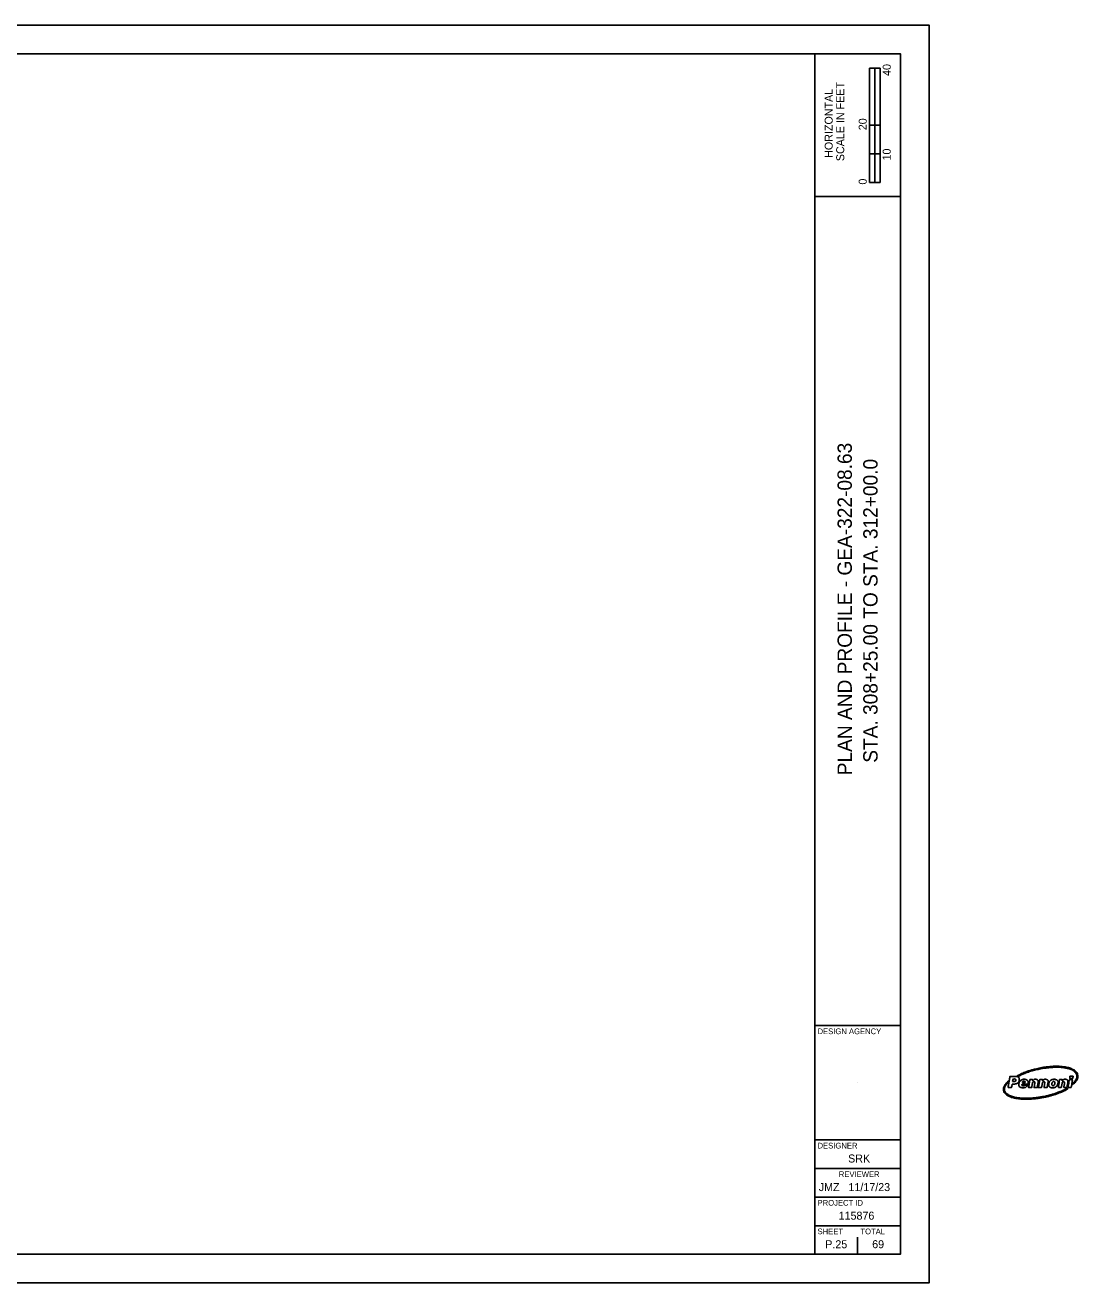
# Model space of a CAD drawing. Extents: x -0.2 to 36.6, y 0 to 22.
# Drawn here: x 18.19 to 36.6, y 0 to 22 of the extents above; entities that cross this region are included whole.
import ezdxf

# ---------------------------------------------------------------- set-up
doc = ezdxf.new("R2010")
doc.units = 0
for name, color, linetype in [('SH_Border', 7, 'Continuous'), ('SH_Cut_Line', 7, 'Continuous'), ('SH_Data', 7, 'Continuous')]:
    doc.layers.add(name, color=color, linetype=linetype)

msp = doc.modelspace()

# ---------------------------------------------------------------- linework, layer by layer
at = {"layer": 'SH_Border'}
for p, q in [((32, 0.5), (32, 21.5)), ((32, 19), (33.5, 19)), ((32, 4.5), (33.5, 4.5)), ((35.683, 3.503), (35.633, 3.503)), ((32, 2.5), (33.5, 2.5)), ((32, 2), (33.5, 2)), ((32, 1.5), (33.5, 1.5)), ((32, 1), (33.5, 1))]:
    msp.add_line(p, q, dxfattribs=at)
msp.add_lwpolyline([(1.5, 21.5), (33.5, 21.5), (33.5, 0.5), (1.5, 0.5)], close=True, dxfattribs=at)
for points, degree in [([(35.542, 3.621), (35.549, 3.619), (35.555, 3.616), (35.561, 3.615), (35.563, 3.614), (35.566, 3.614), (35.568, 3.615), (35.597, 3.629), (35.625, 3.643), (35.654, 3.655), (35.695, 3.673), (35.738, 3.688), (35.781, 3.701), (35.823, 3.714), (35.865, 3.725), (35.908, 3.734), (35.948, 3.743), (35.988, 3.751), (36.028, 3.756), (36.06, 3.76), (36.092, 3.764), (36.124, 3.767), (36.149, 3.769), (36.175, 3.77), (36.2, 3.771), (36.255, 3.772), (36.31, 3.77), (36.365, 3.762), (36.394, 3.758), (36.424, 3.752), (36.452, 3.742), (36.488, 3.731), (36.521, 3.717), (36.549, 3.691), (36.564, 3.678), (36.576, 3.661), (36.581, 3.641), (36.586, 3.624), (36.588, 3.607), (36.585, 3.589), (36.581, 3.569), (36.571, 3.552), (36.559, 3.536), (36.547, 3.521), (36.533, 3.508), (36.518, 3.495), (36.516, 3.494), (36.515, 3.492), (36.514, 3.49), (36.513, 3.485), (36.512, 3.479), (36.511, 3.473), (36.511, 3.471), (36.51, 3.469), (36.51, 3.465), (36.534, 3.485), (36.557, 3.505), (36.575, 3.529), (36.584, 3.54), (36.592, 3.553), (36.597, 3.566), (36.604, 3.585), (36.604, 3.604), (36.602, 3.623), (36.598, 3.658), (36.582, 3.685), (36.556, 3.708), (36.532, 3.728), (36.505, 3.741), (36.475, 3.752), (36.438, 3.766), (36.4, 3.774), (36.361, 3.779), (36.326, 3.784), (36.291, 3.787), (36.255, 3.788), (36.199, 3.789), (36.143, 3.787), (36.087, 3.781), (36.056, 3.777), (36.025, 3.773), (35.994, 3.768), (35.949, 3.761), (35.904, 3.752), (35.86, 3.74), (35.799, 3.725), (35.74, 3.707), (35.681, 3.684), (35.641, 3.669), (35.601, 3.651), (35.562, 3.631), (35.555, 3.628), (35.549, 3.625), (35.542, 3.621)], 3), ([(35.542, 3.621), (35.549, 3.625), (35.555, 3.628), (35.562, 3.631), (35.601, 3.651), (35.641, 3.669), (35.681, 3.684), (35.74, 3.707), (35.799, 3.725), (35.86, 3.74), (35.904, 3.752), (35.949, 3.761), (35.994, 3.768), (36.025, 3.773), (36.056, 3.777), (36.087, 3.781), (36.143, 3.787), (36.199, 3.789), (36.255, 3.788), (36.291, 3.787), (36.326, 3.784), (36.361, 3.779), (36.4, 3.774), (36.438, 3.766), (36.475, 3.752), (36.505, 3.741), (36.532, 3.728), (36.556, 3.708), (36.582, 3.685), (36.598, 3.658), (36.602, 3.623), (36.604, 3.604), (36.604, 3.585), (36.597, 3.566), (36.592, 3.553), (36.584, 3.54), (36.575, 3.529), (36.557, 3.505), (36.534, 3.485), (36.51, 3.465), (36.51, 3.469), (36.511, 3.471), (36.511, 3.473), (36.512, 3.479), (36.513, 3.485), (36.514, 3.49), (36.515, 3.492), (36.516, 3.494), (36.518, 3.495), (36.533, 3.508), (36.547, 3.521), (36.559, 3.536), (36.571, 3.552), (36.581, 3.569), (36.585, 3.589), (36.588, 3.607), (36.586, 3.624), (36.581, 3.641), (36.576, 3.661), (36.564, 3.678), (36.549, 3.691), (36.521, 3.717), (36.488, 3.731), (36.452, 3.742), (36.424, 3.752), (36.394, 3.758), (36.365, 3.762), (36.31, 3.77), (36.255, 3.772), (36.2, 3.771), (36.175, 3.77), (36.149, 3.769), (36.124, 3.767), (36.092, 3.764), (36.06, 3.76), (36.028, 3.756), (35.988, 3.751), (35.948, 3.743), (35.908, 3.734), (35.865, 3.725), (35.823, 3.714), (35.781, 3.701), (35.738, 3.688), (35.695, 3.673), (35.654, 3.655), (35.625, 3.643), (35.597, 3.629), (35.568, 3.615), (35.566, 3.614), (35.563, 3.614), (35.561, 3.615), (35.555, 3.616), (35.549, 3.619), (35.542, 3.621)], 3), ([(36.43, 3.392), (36.43, 3.392), (36.43, 3.393), (36.43, 3.393), (36.42, 3.393), (36.41, 3.393), (36.4, 3.393), (36.398, 3.393), (36.395, 3.392), (36.393, 3.391), (36.356, 3.372), (36.317, 3.355), (36.278, 3.34), (36.22, 3.317), (36.161, 3.298), (36.101, 3.283), (36.058, 3.271), (36.015, 3.262), (35.971, 3.254), (35.946, 3.25), (35.921, 3.246), (35.896, 3.242), (35.871, 3.239), (35.845, 3.236), (35.82, 3.234), (35.795, 3.232), (35.771, 3.23), (35.747, 3.23), (35.719, 3.229), (35.691, 3.228), (35.663, 3.229), (35.632, 3.231), (35.601, 3.233), (35.57, 3.236), (35.532, 3.24), (35.494, 3.248), (35.458, 3.259), (35.426, 3.269), (35.396, 3.282), (35.369, 3.302), (35.353, 3.314), (35.338, 3.329), (35.329, 3.348), (35.317, 3.374), (35.318, 3.4), (35.329, 3.427), (35.338, 3.45), (35.352, 3.47), (35.369, 3.488), (35.374, 3.494), (35.38, 3.5), (35.38, 3.509), (35.381, 3.514), (35.382, 3.52), (35.383, 3.526), (35.382, 3.525), (35.381, 3.525), (35.38, 3.524), (35.371, 3.514), (35.361, 3.505), (35.352, 3.494), (35.332, 3.472), (35.317, 3.448), (35.308, 3.419), (35.304, 3.402), (35.302, 3.385), (35.305, 3.368), (35.31, 3.341), (35.325, 3.319), (35.344, 3.301), (35.367, 3.28), (35.394, 3.266), (35.422, 3.254), (35.469, 3.235), (35.519, 3.225), (35.569, 3.219), (35.599, 3.216), (35.631, 3.214), (35.662, 3.212), (35.704, 3.211), (35.746, 3.211), (35.788, 3.215), (35.823, 3.217), (35.857, 3.221), (35.891, 3.225), (35.922, 3.229), (35.952, 3.234), (35.983, 3.239), (36.037, 3.249), (36.091, 3.261), (36.144, 3.276), (36.189, 3.289), (36.234, 3.304), (36.278, 3.321), (36.321, 3.338), (36.363, 3.356), (36.404, 3.377), (36.413, 3.382), (36.421, 3.387), (36.43, 3.392)], 3), ([(36.43, 3.392), (36.421, 3.387), (36.413, 3.382), (36.404, 3.377), (36.363, 3.356), (36.321, 3.338), (36.278, 3.321), (36.234, 3.304), (36.189, 3.289), (36.144, 3.276), (36.091, 3.261), (36.037, 3.249), (35.983, 3.239), (35.952, 3.234), (35.922, 3.229), (35.891, 3.225), (35.857, 3.221), (35.823, 3.217), (35.788, 3.215), (35.746, 3.211), (35.704, 3.211), (35.662, 3.212), (35.631, 3.214), (35.599, 3.216), (35.569, 3.219), (35.519, 3.225), (35.469, 3.235), (35.422, 3.254), (35.394, 3.266), (35.367, 3.28), (35.344, 3.301), (35.325, 3.319), (35.31, 3.341), (35.305, 3.368), (35.302, 3.385), (35.304, 3.402), (35.308, 3.419), (35.317, 3.448), (35.332, 3.472), (35.352, 3.494), (35.361, 3.505), (35.371, 3.514), (35.38, 3.524), (35.381, 3.525), (35.382, 3.525), (35.383, 3.526), (35.382, 3.52), (35.381, 3.514), (35.38, 3.509), (35.38, 3.5), (35.374, 3.494), (35.369, 3.488), (35.352, 3.47), (35.338, 3.45), (35.329, 3.427), (35.318, 3.4), (35.317, 3.374), (35.329, 3.348), (35.338, 3.329), (35.353, 3.314), (35.369, 3.302), (35.396, 3.282), (35.426, 3.269), (35.458, 3.259), (35.494, 3.248), (35.532, 3.24), (35.57, 3.236), (35.601, 3.233), (35.632, 3.231), (35.663, 3.229), (35.691, 3.228), (35.719, 3.229), (35.747, 3.23), (35.771, 3.23), (35.795, 3.232), (35.82, 3.234), (35.845, 3.236), (35.871, 3.239), (35.896, 3.242), (35.921, 3.246), (35.946, 3.25), (35.971, 3.254), (36.015, 3.262), (36.058, 3.271), (36.101, 3.283), (36.161, 3.298), (36.22, 3.317), (36.278, 3.34), (36.317, 3.355), (36.356, 3.372), (36.393, 3.391), (36.395, 3.392), (36.398, 3.393), (36.4, 3.393), (36.41, 3.393), (36.42, 3.393), (36.43, 3.393), (36.43, 3.393), (36.43, 3.392), (36.43, 3.392)], 3), ([(35.554, 3.602), (35.541, 3.608), (35.528, 3.61), (35.514, 3.61), (35.482, 3.611), (35.45, 3.61), (35.419, 3.61), (35.417, 3.61), (35.416, 3.61), (35.415, 3.608), (35.411, 3.586), (35.408, 3.565), (35.404, 3.543), (35.398, 3.509), (35.392, 3.474), (35.386, 3.439), (35.384, 3.432), (35.383, 3.424), (35.382, 3.417)], 3), ([(35.455, 3.477), (35.463, 3.477), (35.47, 3.477), (35.477, 3.477), (35.49, 3.477), (35.503, 3.477), (35.515, 3.48), (35.532, 3.483), (35.547, 3.49), (35.559, 3.502), (35.574, 3.518), (35.58, 3.537), (35.58, 3.559), (35.581, 3.578), (35.572, 3.593), (35.554, 3.602)], 3), ([(35.463, 3.522), (35.466, 3.536), (35.468, 3.55), (35.47, 3.563), (35.471, 3.564), (35.472, 3.565), (35.473, 3.565), (35.484, 3.565), (35.496, 3.567), (35.507, 3.563), (35.517, 3.56), (35.521, 3.554), (35.519, 3.543)], 3), ([(35.519, 3.543), (35.517, 3.531), (35.508, 3.523), (35.495, 3.522), (35.485, 3.522), (35.474, 3.522), (35.463, 3.522)], 3), ([(35.735, 3.508), (35.731, 3.533), (35.718, 3.55), (35.694, 3.557), (35.681, 3.562), (35.667, 3.562), (35.654, 3.561), (35.632, 3.558), (35.613, 3.549), (35.597, 3.532), (35.583, 3.517), (35.575, 3.5), (35.573, 3.479), (35.57, 3.45), (35.582, 3.426), (35.611, 3.417), (35.627, 3.412), (35.644, 3.411), (35.66, 3.414), (35.678, 3.416), (35.694, 3.422), (35.708, 3.434), (35.716, 3.441), (35.722, 3.449), (35.726, 3.459)], 3), ([(35.633, 3.503), (35.634, 3.515), (35.644, 3.525), (35.656, 3.527), (35.662, 3.528), (35.668, 3.528), (35.673, 3.525), (35.681, 3.521), (35.685, 3.513), (35.683, 3.503)], 3), ([(35.741, 3.416), (35.741, 3.415), (35.742, 3.415), (35.743, 3.415), (35.76, 3.415), (35.777, 3.415), (35.794, 3.415), (35.796, 3.415), (35.796, 3.416), (35.797, 3.418), (35.798, 3.426), (35.799, 3.435), (35.801, 3.443), (35.804, 3.46), (35.807, 3.478), (35.811, 3.495), (35.813, 3.505), (35.817, 3.513), (35.827, 3.515), (35.84, 3.519), (35.854, 3.516), (35.852, 3.497), (35.85, 3.482), (35.847, 3.468), (35.845, 3.454), (35.843, 3.441), (35.84, 3.428), (35.838, 3.416), (35.839, 3.415), (35.839, 3.415), (35.84, 3.415), (35.857, 3.415), (35.874, 3.415), (35.891, 3.415), (35.894, 3.415), (35.894, 3.416), (35.894, 3.419), (35.898, 3.442), (35.903, 3.466), (35.907, 3.49), (35.909, 3.502), (35.911, 3.515), (35.91, 3.527), (35.907, 3.543), (35.898, 3.554), (35.882, 3.558), (35.861, 3.564), (35.841, 3.56), (35.824, 3.545), (35.82, 3.542), (35.816, 3.538), (35.812, 3.535), (35.814, 3.542), (35.815, 3.549), (35.816, 3.557), (35.8, 3.557), (35.783, 3.557), (35.767, 3.556), (35.766, 3.556), (35.765, 3.555), (35.765, 3.554), (35.764, 3.55), (35.763, 3.545), (35.763, 3.541), (35.757, 3.511), (35.752, 3.48), (35.747, 3.45), (35.745, 3.438), (35.743, 3.427), (35.741, 3.416)], 3), ([(35.741, 3.416), (35.743, 3.427), (35.745, 3.438), (35.747, 3.45), (35.752, 3.48), (35.757, 3.511), (35.763, 3.541), (35.763, 3.545), (35.764, 3.55), (35.765, 3.554), (35.765, 3.555), (35.766, 3.556), (35.767, 3.556), (35.783, 3.557), (35.8, 3.557), (35.816, 3.557), (35.815, 3.549), (35.814, 3.542), (35.812, 3.535), (35.816, 3.538), (35.82, 3.542), (35.824, 3.545), (35.841, 3.56), (35.861, 3.564), (35.882, 3.558), (35.898, 3.554), (35.907, 3.543), (35.91, 3.527), (35.911, 3.515), (35.909, 3.502), (35.907, 3.49), (35.903, 3.466), (35.898, 3.442), (35.894, 3.419), (35.894, 3.416), (35.894, 3.415), (35.891, 3.415), (35.874, 3.415), (35.857, 3.415), (35.84, 3.415), (35.839, 3.415), (35.839, 3.415), (35.838, 3.416), (35.84, 3.428), (35.843, 3.441), (35.845, 3.454), (35.847, 3.468), (35.85, 3.482), (35.852, 3.497), (35.854, 3.516), (35.84, 3.519), (35.827, 3.515), (35.817, 3.513), (35.813, 3.505), (35.811, 3.495), (35.807, 3.478), (35.804, 3.46), (35.801, 3.443), (35.799, 3.435), (35.798, 3.426), (35.797, 3.418), (35.796, 3.416), (35.796, 3.415), (35.794, 3.415), (35.777, 3.415), (35.76, 3.415), (35.743, 3.415), (35.742, 3.415), (35.741, 3.415), (35.741, 3.416)], 3), ([(35.914, 3.416), (35.914, 3.415), (35.914, 3.415), (35.915, 3.415), (35.932, 3.415), (35.949, 3.415), (35.967, 3.415), (35.968, 3.415), (35.969, 3.417), (35.97, 3.418), (35.973, 3.435), (35.976, 3.452), (35.979, 3.469), (35.981, 3.479), (35.982, 3.49), (35.985, 3.5), (35.989, 3.513), (36.001, 3.519), (36.014, 3.516), (36.02, 3.515), (36.023, 3.511), (36.024, 3.505), (36.025, 3.502), (36.025, 3.499), (36.025, 3.496), (36.023, 3.485), (36.021, 3.473), (36.019, 3.462), (36.017, 3.447), (36.014, 3.431), (36.011, 3.416), (36.012, 3.415), (36.012, 3.415), (36.012, 3.415), (36.029, 3.415), (36.047, 3.415), (36.064, 3.415), (36.065, 3.415), (36.067, 3.417), (36.067, 3.418), (36.071, 3.441), (36.075, 3.463), (36.079, 3.485), (36.081, 3.497), (36.083, 3.509), (36.083, 3.522), (36.083, 3.537), (36.077, 3.55), (36.061, 3.556), (36.041, 3.564), (36.021, 3.562), (36.003, 3.55), (35.997, 3.545), (35.991, 3.54), (35.985, 3.535), (35.987, 3.543), (35.988, 3.549), (35.989, 3.557), (35.973, 3.557), (35.957, 3.557), (35.941, 3.557), (35.938, 3.557), (35.938, 3.555), (35.938, 3.553), (35.934, 3.529), (35.929, 3.505), (35.925, 3.481), (35.921, 3.46), (35.918, 3.438), (35.914, 3.416)], 3), ([(35.914, 3.416), (35.918, 3.438), (35.921, 3.46), (35.925, 3.481), (35.929, 3.505), (35.934, 3.529), (35.938, 3.553), (35.938, 3.555), (35.938, 3.557), (35.941, 3.557), (35.957, 3.557), (35.973, 3.557), (35.989, 3.557), (35.988, 3.549), (35.987, 3.543), (35.985, 3.535), (35.991, 3.54), (35.997, 3.545), (36.003, 3.55), (36.021, 3.562), (36.041, 3.564), (36.061, 3.556), (36.077, 3.55), (36.083, 3.537), (36.083, 3.522), (36.083, 3.509), (36.081, 3.497), (36.079, 3.485), (36.075, 3.463), (36.071, 3.441), (36.067, 3.418), (36.067, 3.417), (36.065, 3.415), (36.064, 3.415), (36.047, 3.415), (36.029, 3.415), (36.012, 3.415), (36.012, 3.415), (36.012, 3.415), (36.011, 3.416), (36.014, 3.431), (36.017, 3.447), (36.019, 3.462), (36.021, 3.473), (36.023, 3.485), (36.025, 3.496), (36.025, 3.499), (36.025, 3.502), (36.024, 3.505), (36.023, 3.511), (36.02, 3.515), (36.014, 3.516), (36.001, 3.519), (35.989, 3.513), (35.985, 3.5), (35.982, 3.49), (35.981, 3.479), (35.979, 3.469), (35.976, 3.452), (35.973, 3.435), (35.97, 3.418), (35.969, 3.417), (35.968, 3.415), (35.967, 3.415), (35.949, 3.415), (35.932, 3.415), (35.915, 3.415), (35.914, 3.415), (35.914, 3.415), (35.914, 3.416)], 3), ([(36.257, 3.508), (36.255, 3.53), (36.244, 3.545), (36.224, 3.554), (36.205, 3.562), (36.185, 3.562), (36.165, 3.558), (36.141, 3.553), (36.122, 3.541), (36.108, 3.52), (36.107, 3.518), (36.106, 3.515), (36.105, 3.513), (36.104, 3.511), (36.103, 3.509), (36.102, 3.507), (36.097, 3.496), (36.094, 3.484), (36.094, 3.472), (36.094, 3.47), (36.094, 3.467), (36.094, 3.465), (36.094, 3.457), (36.096, 3.45), (36.099, 3.444), (36.099, 3.443), (36.1, 3.441), (36.1, 3.44), (36.101, 3.439), (36.102, 3.438), (36.102, 3.437), (36.105, 3.434), (36.107, 3.43), (36.111, 3.427), (36.113, 3.426), (36.115, 3.424), (36.117, 3.423), (36.117, 3.422), (36.118, 3.422), (36.119, 3.422), (36.12, 3.421), (36.121, 3.42), (36.122, 3.42), (36.124, 3.419), (36.126, 3.418), (36.128, 3.417), (36.139, 3.412), (36.151, 3.411), (36.163, 3.41)], 3), ([(36.15, 3.471), (36.151, 3.487), (36.153, 3.501), (36.162, 3.513), (36.167, 3.519), (36.174, 3.523), (36.182, 3.523), (36.191, 3.523), (36.197, 3.52), (36.199, 3.511), (36.2, 3.505), (36.201, 3.498), (36.201, 3.491)], 3), ([(36.284, 3.556), (36.276, 3.509), (36.268, 3.462), (36.26, 3.415), (36.279, 3.415), (36.297, 3.415), (36.315, 3.415), (36.318, 3.43), (36.32, 3.444), (36.323, 3.458), (36.325, 3.471), (36.327, 3.484), (36.33, 3.496), (36.333, 3.51), (36.343, 3.517), (36.356, 3.517), (36.365, 3.516), (36.37, 3.511), (36.371, 3.503), (36.371, 3.5), (36.371, 3.497), (36.371, 3.494), (36.368, 3.475), (36.364, 3.456), (36.361, 3.437), (36.36, 3.43), (36.359, 3.423), (36.357, 3.415), (36.376, 3.415), (36.394, 3.415), (36.413, 3.415), (36.413, 3.417), (36.413, 3.418), (36.413, 3.419), (36.417, 3.44), (36.421, 3.462), (36.425, 3.483), (36.427, 3.497), (36.43, 3.51), (36.429, 3.525), (36.428, 3.541), (36.419, 3.553), (36.403, 3.558), (36.378, 3.565), (36.357, 3.559), (36.338, 3.541), (36.336, 3.539), (36.334, 3.537), (36.332, 3.535), (36.332, 3.535), (36.332, 3.535), (36.332, 3.536), (36.333, 3.542), (36.334, 3.549), (36.335, 3.556), (36.318, 3.556), (36.301, 3.556), (36.284, 3.556)], 3), ([(36.284, 3.556), (36.301, 3.556), (36.318, 3.556), (36.335, 3.556), (36.334, 3.549), (36.333, 3.542), (36.332, 3.536), (36.332, 3.535), (36.332, 3.535), (36.332, 3.535), (36.334, 3.537), (36.336, 3.539), (36.338, 3.541), (36.357, 3.559), (36.378, 3.565), (36.403, 3.558), (36.419, 3.553), (36.428, 3.541), (36.429, 3.525), (36.43, 3.51), (36.427, 3.497), (36.425, 3.483), (36.421, 3.462), (36.417, 3.44), (36.413, 3.419), (36.413, 3.418), (36.413, 3.417), (36.413, 3.415), (36.394, 3.415), (36.376, 3.415), (36.357, 3.415), (36.359, 3.423), (36.36, 3.43), (36.361, 3.437), (36.364, 3.456), (36.368, 3.475), (36.371, 3.494), (36.371, 3.497), (36.371, 3.5), (36.371, 3.503), (36.37, 3.511), (36.365, 3.516), (36.356, 3.517), (36.343, 3.517), (36.333, 3.51), (36.33, 3.496), (36.327, 3.484), (36.325, 3.471), (36.323, 3.458), (36.32, 3.444), (36.318, 3.43), (36.315, 3.415), (36.297, 3.415), (36.279, 3.415), (36.26, 3.415), (36.268, 3.462), (36.276, 3.509), (36.284, 3.556)], 3), ([(36.487, 3.417), (36.469, 3.417), (36.451, 3.417), (36.432, 3.417), (36.44, 3.464), (36.448, 3.51), (36.456, 3.557), (36.475, 3.557), (36.493, 3.557), (36.512, 3.557), (36.504, 3.51), (36.495, 3.464), (36.487, 3.417)], 3), ([(36.487, 3.417), (36.495, 3.464), (36.504, 3.51), (36.512, 3.557), (36.493, 3.557), (36.475, 3.557), (36.456, 3.557), (36.448, 3.51), (36.44, 3.464), (36.432, 3.417), (36.451, 3.417), (36.469, 3.417), (36.487, 3.417)], 3), ([(36.522, 3.615), (36.52, 3.603), (36.518, 3.591), (36.515, 3.578), (36.515, 3.577), (36.514, 3.576), (36.513, 3.576), (36.495, 3.576), (36.478, 3.576), (36.46, 3.576), (36.461, 3.586), (36.463, 3.595), (36.465, 3.604), (36.465, 3.606), (36.466, 3.609), (36.466, 3.611), (36.466, 3.615), (36.467, 3.615), (36.471, 3.615), (36.487, 3.615), (36.502, 3.615), (36.518, 3.615), (36.519, 3.615), (36.52, 3.615), (36.522, 3.615)], 3), ([(36.522, 3.615), (36.52, 3.615), (36.519, 3.615), (36.518, 3.615), (36.502, 3.615), (36.487, 3.615), (36.471, 3.615), (36.467, 3.615), (36.466, 3.615), (36.466, 3.611), (36.466, 3.609), (36.465, 3.606), (36.465, 3.604), (36.463, 3.595), (36.461, 3.586), (36.46, 3.576), (36.478, 3.576), (36.495, 3.576), (36.513, 3.576), (36.514, 3.576), (36.515, 3.577), (36.515, 3.578), (36.518, 3.591), (36.52, 3.603), (36.522, 3.615)], 3), ([(35.382, 3.417), (35.383, 3.417), (35.383, 3.417), (35.384, 3.417), (35.403, 3.417), (35.423, 3.417), (35.442, 3.417), (35.445, 3.417), (35.445, 3.418), (35.445, 3.42), (35.447, 3.431), (35.449, 3.442), (35.451, 3.454), (35.453, 3.461), (35.454, 3.469), (35.455, 3.477)], 3), ([(35.726, 3.459), (35.709, 3.459), (35.692, 3.459), (35.675, 3.458), (35.674, 3.458), (35.673, 3.457), (35.672, 3.457), (35.668, 3.454), (35.664, 3.45), (35.66, 3.448), (35.643, 3.442), (35.626, 3.451), (35.627, 3.47), (35.627, 3.474), (35.628, 3.475), (35.632, 3.475), (35.664, 3.475), (35.696, 3.475), (35.729, 3.475), (35.73, 3.475), (35.732, 3.475), (35.734, 3.475)], 3), ([(35.734, 3.475), (35.736, 3.486), (35.737, 3.497), (35.735, 3.508)], 2), ([(36.201, 3.491), (36.2, 3.481), (36.197, 3.471), (36.192, 3.462), (36.186, 3.452), (36.176, 3.447), (36.166, 3.449), (36.159, 3.45), (36.154, 3.453), (36.152, 3.459), (36.151, 3.464), (36.15, 3.469), (36.15, 3.471)], 3), ([(36.163, 3.41), (36.17, 3.411), (36.177, 3.412), (36.184, 3.413), (36.203, 3.416), (36.22, 3.425), (36.233, 3.439), (36.251, 3.459), (36.258, 3.482), (36.257, 3.508)], 3)]:
    msp.add_open_spline(points, degree=degree, dxfattribs=at)
at = {"layer": 'SH_Cut_Line'}
msp.add_lwpolyline([(0, 0), (34, 0), (34, 22), (0, 22)], close=True, dxfattribs=at)
at = {"layer": 'SH_Data'}
for p, q in [((32.957, 19.25), (32.957, 21.25)), ((33.144, 21.25), (32.957, 21.25)), ((32.957, 20.25), (32.957, 21.25)), ((32.957, 21.25), (33.05, 21.25)), ((33.05, 21.25), (33.051, 21.25)), ((33.051, 21.25), (33.051, 20.25)), ((33.144, 21.25), (33.144, 19.25)), ((33.051, 20.25), (32.957, 20.25)), ((33.143, 20.25), (33.05, 20.25)), ((33.05, 20.25), (33.05, 19.75)), ((33.143, 19.75), (33.143, 20.25)), ((33.05, 19.75), (32.957, 19.75)), ((32.957, 19.75), (32.957, 19.25)), ((33.05, 19.25), (33.05, 19.75)), ((33.05, 19.75), (33.143, 19.75)), ((33.144, 19.25), (32.957, 19.25)), ((32.957, 19.25), (33.05, 19.25)), ((32.75, 3.5), (32.75, 3.5)), ((32.375, 0.675), (32.375, 0.675)), ((32.75, 0.5), (32.75, 0.8))]:
    msp.add_line(p, q, dxfattribs=at)

# ---------------------------------------------------------------- texts
for s, height, p in [('40', 0.14, (33.33, 21.112)), ('SCALE IN FEET', 0.14, (32.517, 19.621)), ('HORIZONTAL', 0.14, (32.315, 19.679)), ('20', 0.14, (32.91, 20.162)), ('10', 0.14, (33.33, 19.633)), ('0', 0.14, (32.91, 19.211)), ('PLAN AND PROFILE - GEA-322-08.63', 0.25, (32.65, 8.879)), ('STA. 308+25.00 TO STA. 312+00.0', 0.25, (33.1, 9.098))]:
    msp.add_text(s, height=height, rotation=90, dxfattribs=at).set_placement(p)
for s, height, p in [('DESIGN AGENCY', 0.1, (32.05, 4.35)), ('DESIGNER', 0.1, (32.05, 2.35)), ('SRK', 0.14, (32.585, 2.105)), ('REVIEWER', 0.1, (32.422, 1.85)), ('JMZ', 0.14, (32.071, 1.605)), ('11/17/23', 0.14, (32.591, 1.605)), ('PROJECT ID', 0.1, (32.05, 1.35)), ('115876', 0.14, (32.419, 1.105)), ('SHEET', 0.1, (32.05, 0.85)), ('TOTAL', 0.1, (32.8, 0.85)), ('P.25', 0.14, (32.185, 0.605)), ('69', 0.14, (33.006, 0.606))]:
    msp.add_text(s, height=height, dxfattribs=at).set_placement(p)

doc.saveas('drawing.dxf')
